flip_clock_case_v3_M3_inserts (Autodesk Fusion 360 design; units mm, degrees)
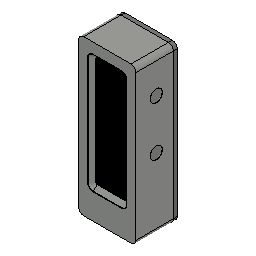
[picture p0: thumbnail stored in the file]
part number: ESP32-C3 supermini
sketch "TFT_PCB_proxy_thickness_1p6_sketch" plane through (0, 0, 0) normal (0, 0, 1) x axis (1, 0, 0)
  line L1 (21.08, 0) -> (0, 0)
  line L2 (21.08, 73.15) -> (21.08, 0)
  line L3 (0, 73.15) -> (21.08, 73.15)
  line L4 (0, 0) -> (0, 73.15)
extrude "Extrude1" new body sketch "TFT_PCB_proxy_thickness_1p6_sketch" along normal blind 1.6 bodies "TFT_PCB_proxy_thickness_1p6"
sketch "M2_hole_locations" plane through (0, 0, 0) normal (0, 0, 1) x axis (1, 0, 0)
  circle C1 centre (2.41, 2.41) radius 1.25
  circle C2 centre (18.67, 2.41) radius 1.25
extrude "Extrude2" cut sketch "M2_hole_locations" blind 5 from offset -1
sketch "LCD_proxy_sketch" plane through (0, 0, 0) normal (0, 0, 1) x axis (1, 0, 0)
  line L1 (18.98, 8.4) -> (1.98, 8.4)
  line L2 (18.98, 68.95) -> (18.98, 8.4)
  line L3 (1.98, 68.95) -> (18.98, 68.95)
  line L4 (1.98, 8.4) -> (1.98, 68.95)
extrude "Extrude3" new body sketch "LCD_proxy_sketch" blind 1.5 from offset 1.6 bodies "LCD_proxy"
sketch "frame_part_1_sketch" plane through (0, 0, 0) normal (0, 0, 1) x axis (1, 0, 0)
  line L1 (1.3, 0) -> (-1.35, 0)
  line L2 (1.3, 69.2) -> (1.3, 0)
  line L3 (-1.35, 69.2) -> (1.3, 69.2)
  line L4 (-1.35, 0) -> (-1.35, 69.2)
extrude "Extrude1" new body sketch "frame_part_1_sketch" blind 3 from offset -4 bodies "01_KHUNG_HA_ESP"
sketch "frame_part_2_sketch" plane through (0, 0, 0) normal (0, 0, 1) x axis (1, 0, 0)
  line L1 (22.43, 0) -> (19.78, 0)
  line L2 (22.43, 69.2) -> (22.43, 0)
  line L3 (19.78, 69.2) -> (22.43, 69.2)
  line L4 (19.78, 0) -> (19.78, 69.2)
extrude "Extrude2" new body sketch "frame_part_2_sketch" blind 3 from offset -4 bodies "frame_part_2"
sketch "frame_part_3_sketch" plane through (0, 0, 0) normal (0, 0, 1) x axis (1, 0, 0)
  line L1 (1.3, 0) -> (0, 0)
  line L2 (1.3, 69.2) -> (1.3, 0)
  line L3 (0, 69.2) -> (1.3, 69.2)
  line L4 (0, 0) -> (0, 69.2)
extrude "Extrude3" new body sketch "frame_part_3_sketch" blind 1 from offset -1 bodies "frame_part_3"
sketch "frame_part_4_sketch" plane through (0, 0, 0) normal (0, 0, 1) x axis (1, 0, 0)
  line L1 (21.08, 0) -> (19.78, 0)
  line L2 (21.08, 69.2) -> (21.08, 0)
  line L3 (19.78, 69.2) -> (21.08, 69.2)
  line L4 (19.78, 0) -> (19.78, 69.2)
extrude "Extrude4" new body sketch "frame_part_4_sketch" blind 1 from offset -1 bodies "frame_part_4"
sketch "frame_part_5_sketch" plane through (0, 0, 0) normal (0, 0, 1) x axis (1, 0, 0)
  line L1 (22.43, 0) -> (-1.35, 0)
  line L2 (22.43, 5.2) -> (22.43, 0)
  line L3 (-1.35, 5.2) -> (22.43, 5.2)
  line L4 (-1.35, 0) -> (-1.35, 5.2)
extrude "Extrude5" new body sketch "frame_part_5_sketch" blind 4 from offset -4 bodies "frame_part_5"
sketch "frame_part_6_sketch" plane through (0, 0, 0) normal (0, 0, 1) x axis (1, 0, 0)
  line L1 (22.43, 66) -> (-1.35, 66)
  line L2 (22.43, 69.2) -> (22.43, 66)
  line L3 (-1.35, 69.2) -> (22.43, 69.2)
  line L4 (-1.35, 66) -> (-1.35, 69.2)
extrude "Extrude6" new body sketch "frame_part_6_sketch" blind 4 from offset -4 bodies "frame_part_6"
sketch "frame_part_7_sketch" plane through (0, 0, 0) normal (0, 0, 1) x axis (1, 0, 0)
  line L1 (22.43, 20.8) -> (-1.35, 20.8)
  line L2 (22.43, 24.8) -> (22.43, 20.8)
  line L3 (-1.35, 24.8) -> (22.43, 24.8)
  line L4 (-1.35, 20.8) -> (-1.35, 24.8)
extrude "Extrude7" new body sketch "frame_part_7_sketch" blind 3 from offset -4 bodies "frame_part_7"
sketch "frame_part_8_sketch" plane through (0, 0, 0) normal (0, 0, 1) x axis (1, 0, 0)
  line L1 (15.88, -1.15) -> (5.2, -1.15)
  line L2 (15.88, 1) -> (15.88, -1.15)
  line L3 (5.2, 1) -> (15.88, 1)
  line L4 (5.2, -1.15) -> (5.2, 1)
extrude "Extrude8" new body sketch "frame_part_8_sketch" blind 2 from offset -4 bodies "frame_part_8"
sketch "frame_part_9_sketch" plane through (0, 0, 0) normal (0, 0, 1) x axis (1, 0, 0)
  line L1 (19.44, -1.15) -> (1.64, -1.15)
  line L2 (19.44, -0.7) -> (19.44, -1.15)
  line L3 (1.64, -0.7) -> (19.44, -0.7)
  line L4 (1.64, -1.15) -> (1.64, -0.7)
extrude "Extrude9" new body sketch "frame_part_9_sketch" blind 4.6 from offset -7.8 bodies "frame_part_9"
sketch "frame_part_10_sketch" plane through (0, 0, 0) normal (0, 0, 1) x axis (1, 0, 0)
  line L1 (4.2, -1.15) -> (1.64, -1.15)
  line L2 (4.2, -0.7) -> (4.2, -1.15)
  line L3 (1.64, -0.7) -> (4.2, -0.7)
  line L4 (1.64, -1.15) -> (1.64, -0.7)
extrude "Extrude10" new body sketch "frame_part_10_sketch" blind 0.4 from offset -8.2 bodies "frame_part_10"
sketch "frame_part_11_sketch" plane through (0, 0, 0) normal (0, 0, 1) x axis (1, 0, 0)
  line L1 (4.2, 21.1) -> (1.64, 21.1)
  line L2 (4.2, 21.55) -> (4.2, 21.1)
  line L3 (1.64, 21.55) -> (4.2, 21.55)
  line L4 (1.64, 21.1) -> (1.64, 21.55)
extrude "Extrude11" new body sketch "frame_part_11_sketch" blind 4.2 from offset -8.2 bodies "frame_part_11"
sketch "frame_part_12_sketch" plane through (0, 0, 0) normal (0, 0, 1) x axis (1, 0, 0)
  line L1 (19.44, -1.15) -> (16.88, -1.15)
  line L2 (19.44, -0.7) -> (19.44, -1.15)
  line L3 (16.88, -0.7) -> (19.44, -0.7)
  line L4 (16.88, -1.15) -> (16.88, -0.7)
extrude "Extrude12" new body sketch "frame_part_12_sketch" blind 0.4 from offset -8.2 bodies "frame_part_12"
sketch "frame_part_13_sketch" plane through (0, 0, 0) normal (0, 0, 1) x axis (1, 0, 0)
  line L1 (19.44, 21.1) -> (16.88, 21.1)
  line L2 (19.44, 21.55) -> (19.44, 21.1)
  line L3 (16.88, 21.55) -> (19.44, 21.55)
  line L4 (16.88, 21.1) -> (16.88, 21.55)
extrude "Extrude13" new body sketch "frame_part_13_sketch" blind 4.2 from offset -8.2 bodies "frame_part_13"
sketch "frame_part_14_sketch" plane through (0, 0, 0) normal (1, 0, 0) x axis (0, 0, -1)
  circle C1 centre (4.1, 9.3) radius 3.9
extrude "Extrude14" new body sketch "frame_part_14_sketch" blind 6 from offset 1.6 bodies "frame_part_14"
sketch "frame_part_15_sketch" plane through (0, 0, 0) normal (1, 0, 0) x axis (0, 0, -1)
  circle C1 centre (4.1, 9.3) radius 3.9
extrude "Extrude15" new body sketch "frame_part_15_sketch" blind 6 from offset 13.48 bodies "frame_part_15"
sketch "frame_part_16_sketch" plane through (0, 0, 0) normal (0, 0, 1) x axis (1, 0, 0)
  line L1 (3, 5.4) -> (0.7, 5.4)
  line L2 (3, 13.2) -> (3, 5.4)
  line L3 (0.7, 13.2) -> (3, 13.2)
  line L4 (0.7, 5.4) -> (0.7, 13.2)
extrude "Extrude16" new body sketch "frame_part_16_sketch" blind 0.6 from offset -0.8 bodies "frame_part_16"
sketch "frame_part_17_sketch" plane through (0, 0, 0) normal (0, 0, 1) x axis (1, 0, 0)
  line L1 (20.38, 5.4) -> (18.08, 5.4)
  line L2 (20.38, 13.2) -> (20.38, 5.4)
  line L3 (18.08, 13.2) -> (20.38, 13.2)
  line L4 (18.08, 5.4) -> (18.08, 13.2)
extrude "Extrude17" new body sketch "frame_part_17_sketch" blind 0.6 from offset -0.8 bodies "frame_part_17"
sketch "frame_part_18_sketch" plane through (0, 0, 0) normal (1, 0, 0) x axis (0, 0, -1)
  circle C1 centre (4.1, 20) radius 3.9
extrude "Extrude18" new body sketch "frame_part_18_sketch" blind 6 from offset 1.6 bodies "frame_part_18"
sketch "frame_part_19_sketch" plane through (0, 0, 0) normal (1, 0, 0) x axis (0, 0, -1)
  circle C1 centre (4.1, 20) radius 3.9
extrude "Extrude19" new body sketch "frame_part_19_sketch" blind 6 from offset 13.48 bodies "frame_part_19"
sketch "frame_part_20_sketch" plane through (0, 0, 0) normal (0, 0, 1) x axis (1, 0, 0)
  line L1 (3, 16.1) -> (0.7, 16.1)
  line L2 (3, 23.9) -> (3, 16.1)
  line L3 (0.7, 23.9) -> (3, 23.9)
  line L4 (0.7, 16.1) -> (0.7, 23.9)
extrude "Extrude20" new body sketch "frame_part_20_sketch" blind 0.6 from offset -0.8 bodies "frame_part_20"
sketch "frame_part_21_sketch" plane through (0, 0, 0) normal (0, 0, 1) x axis (1, 0, 0)
  line L1 (20.38, 16.1) -> (18.08, 16.1)
  line L2 (20.38, 23.9) -> (20.38, 16.1)
  line L3 (18.08, 23.9) -> (20.38, 23.9)
  line L4 (18.08, 16.1) -> (18.08, 23.9)
extrude "Extrude21" new body sketch "frame_part_21_sketch" blind 0.6 from offset -0.8 bodies "frame_part_21"
sketch "frame_part_22_sketch" plane through (0, 0, 0) normal (1, 0, 0) x axis (0, 0, -1)
  circle C1 centre (5, 33) radius 3.9
extrude "Extrude22" new body sketch "frame_part_22_sketch" blind 6.5 from offset -1.35 bodies "frame_part_22"
sketch "frame_part_23_sketch" plane through (0, 0, 0) normal (1, 0, 0) x axis (0, 0, -1)
  circle C1 centre (5, 33) radius 3.9
extrude "Extrude23" new body sketch "frame_part_23_sketch" blind 6.5 from offset 15.93 bodies "frame_part_23"
sketch "frame_part_24_sketch" plane through (0, 0, 0) normal (1, 0, 0) x axis (0, 0, -1)
  circle C1 centre (5, 58) radius 3.9
extrude "Extrude24" new body sketch "frame_part_24_sketch" blind 6.5 from offset -1.35 bodies "frame_part_24"
sketch "frame_part_25_sketch" plane through (0, 0, 0) normal (1, 0, 0) x axis (0, 0, -1)
  circle C1 centre (5, 58) radius 3.9
extrude "Extrude25" new body sketch "frame_part_25_sketch" blind 6.5 from offset 15.93 bodies "frame_part_25"
sketch "frame_part_26_sketch" plane through (0, 0, 0) normal (0, 0, 1) x axis (1, 0, 0)
  circle C1 centre (3, 42) radius 3.9
extrude "Extrude26" new body sketch "frame_part_26_sketch" blind 8.5 from offset -12.4 bodies "frame_part_26"
sketch "frame_part_27_sketch" plane through (0, 0, 0) normal (0, 0, 1) x axis (1, 0, 0)
  circle C1 centre (18.08, 42) radius 3.9
extrude "Extrude27" new body sketch "frame_part_27_sketch" blind 8.5 from offset -12.4 bodies "frame_part_27"
sketch "frame_part_28_sketch" plane through (0, 0, 0) normal (0, 0, 1) x axis (1, 0, 0)
  circle C1 centre (3, 66) radius 3.9
extrude "Extrude28" new body sketch "frame_part_28_sketch" blind 8.5 from offset -12.4 bodies "frame_part_28"
sketch "frame_part_29_sketch" plane through (0, 0, 0) normal (0, 0, 1) x axis (1, 0, 0)
  circle C1 centre (18.08, 66) radius 3.9
extrude "Extrude29" new body sketch "frame_part_29_sketch" blind 8.5 from offset -12.4 bodies "frame_part_29"
combine "Combine1" bodies "frame_part_2", "frame_part_3", "frame_part_4", "frame_part_5", "frame_part_6", "frame_part_7", "frame_part_8", "frame_part_9"
sketch "frame_cut_1_sketch" plane through (0, 0, 0) normal (0, 0, 1) x axis (1, 0, 0)
  circle C1 centre (2.41, 2.41) radius 1.1
extrude "Extrude30" cut sketch "frame_cut_1_sketch" blind 12 from offset -10
sketch "frame_cut_2_sketch" plane through (0, 0, 0) normal (0, 0, 1) x axis (1, 0, 0)
  circle C1 centre (18.67, 2.41) radius 1.1
extrude "Extrude31" cut sketch "frame_cut_2_sketch" blind 12 from offset -10
sketch "TFT_M2_nut_pocket_1_sketch" plane through (0, 0, 0) normal (0, 0, 1) x axis (1, 0, 0)
  line L1 (3.6224, 4.51) -> (4.8349, 2.41)
  line L2 (1.1976, 4.51) -> (3.6224, 4.51)
  line L3 (-0.0149, 2.41) -> (1.1976, 4.51)
  line L4 (1.1976, 0.31) -> (-0.0149, 2.41)
  line L5 (3.6224, 0.31) -> (1.1976, 0.31)
  line L6 (4.8349, 2.41) -> (3.6224, 0.31)
extrude "Extrude32" cut sketch "TFT_M2_nut_pocket_1_sketch" blind 1.75 from offset -4
sketch "TFT_M2_nut_pocket_2_sketch" plane through (0, 0, 0) normal (0, 0, 1) x axis (1, 0, 0)
  line L1 (19.8824, 4.51) -> (21.0949, 2.41)
  line L2 (17.4576, 4.51) -> (19.8824, 4.51)
  line L3 (16.2451, 2.41) -> (17.4576, 4.51)
  line L4 (17.4576, 0.31) -> (16.2451, 2.41)
  line L5 (19.8824, 0.31) -> (17.4576, 0.31)
  line L6 (21.0949, 2.41) -> (19.8824, 0.31)
extrude "Extrude33" cut sketch "TFT_M2_nut_pocket_2_sketch" blind 1.75 from offset -4
sketch "frame_cut_5_sketch" plane through (0, 0, 0) normal (0, 0, 1) x axis (1, 0, 0)
  line L1 (1.6, 6) -> (-2, 6)
  line L2 (1.6, 12.6) -> (1.6, 6)
  line L3 (-2, 12.6) -> (1.6, 12.6)
  line L4 (-2, 6) -> (-2, 12.6)
extrude "Extrude34" cut sketch "frame_cut_5_sketch" blind 7.2 from offset -8
sketch "frame_cut_6_sketch" plane through (0, 0, 0) normal (0, 0, 1) x axis (1, 0, 0)
  line L1 (23.1, 6) -> (19.48, 6)
  line L2 (23.1, 12.6) -> (23.1, 6)
  line L3 (19.48, 12.6) -> (23.1, 12.6)
  line L4 (19.48, 6) -> (19.48, 12.6)
extrude "Extrude35" cut sketch "frame_cut_6_sketch" blind 7.2 from offset -8
sketch "frame_cut_7_sketch" plane through (0, 0, 0) normal (1, 0, 0) x axis (0, 0, -1)
  circle C1 centre (4.1, 9.3) radius 2
extrude "Extrude36" cut sketch "frame_cut_7_sketch" blind 5 from offset 1.6
sketch "frame_cut_8_sketch" plane through (0, 0, 0) normal (1, 0, 0) x axis (0, 0, -1)
  circle C1 centre (4.1, 9.3) radius 2
extrude "Extrude37" cut sketch "frame_cut_8_sketch" blind 5 from offset 14.48
sketch "frame_cut_9_sketch" plane through (0, 0, 0) normal (1, 0, 0) x axis (0, 0, -1)
  circle C1 centre (4.1, 9.3) radius 1.7
extrude "Extrude38" cut sketch "frame_cut_9_sketch" blind 5.3 from offset 1.6
sketch "frame_cut_10_sketch" plane through (0, 0, 0) normal (1, 0, 0) x axis (0, 0, -1)
  circle C1 centre (4.1, 9.3) radius 1.7
extrude "Extrude39" cut sketch "frame_cut_10_sketch" blind 5.3 from offset 14.18
sketch "frame_cut_11_sketch" plane through (0, 0, 0) normal (0, 0, 1) x axis (1, 0, 0)
  line L1 (1.6, 16.7) -> (-2, 16.7)
  line L2 (1.6, 23.3) -> (1.6, 16.7)
  line L3 (-2, 23.3) -> (1.6, 23.3)
  line L4 (-2, 16.7) -> (-2, 23.3)
extrude "Extrude40" cut sketch "frame_cut_11_sketch" blind 7.2 from offset -8
sketch "frame_cut_12_sketch" plane through (0, 0, 0) normal (0, 0, 1) x axis (1, 0, 0)
  line L1 (23.1, 16.7) -> (19.48, 16.7)
  line L2 (23.1, 23.3) -> (23.1, 16.7)
  line L3 (19.48, 23.3) -> (23.1, 23.3)
  line L4 (19.48, 16.7) -> (19.48, 23.3)
extrude "Extrude41" cut sketch "frame_cut_12_sketch" blind 7.2 from offset -8
sketch "frame_cut_13_sketch" plane through (0, 0, 0) normal (1, 0, 0) x axis (0, 0, -1)
  circle C1 centre (4.1, 20) radius 2
extrude "Extrude42" cut sketch "frame_cut_13_sketch" blind 5 from offset 1.6
sketch "frame_cut_14_sketch" plane through (0, 0, 0) normal (1, 0, 0) x axis (0, 0, -1)
  circle C1 centre (4.1, 20) radius 2
extrude "Extrude43" cut sketch "frame_cut_14_sketch" blind 5 from offset 14.48
sketch "frame_cut_15_sketch" plane through (0, 0, 0) normal (1, 0, 0) x axis (0, 0, -1)
  circle C1 centre (4.1, 20) radius 1.7
extrude "Extrude44" cut sketch "frame_cut_15_sketch" blind 5.3 from offset 1.6
sketch "frame_cut_16_sketch" plane through (0, 0, 0) normal (1, 0, 0) x axis (0, 0, -1)
  circle C1 centre (4.1, 20) radius 1.7
extrude "Extrude45" cut sketch "frame_cut_16_sketch" blind 5.3 from offset 14.18
sketch "frame_cut_17_sketch" plane through (0, 0, 0) normal (1, 0, 0) x axis (0, 0, -1)
  circle C1 centre (5, 33) radius 2
extrude "Extrude46" cut sketch "frame_cut_17_sketch" blind 5 from offset -1.35
sketch "frame_cut_18_sketch" plane through (0, 0, 0) normal (1, 0, 0) x axis (0, 0, -1)
  circle C1 centre (5, 33) radius 2
extrude "Extrude47" cut sketch "frame_cut_18_sketch" blind 5 from offset 17.43
sketch "frame_cut_19_sketch" plane through (0, 0, 0) normal (1, 0, 0) x axis (0, 0, -1)
  circle C1 centre (5, 33) radius 1.7
extrude "Extrude48" cut sketch "frame_cut_19_sketch" blind 6 from offset -1.35
sketch "frame_cut_20_sketch" plane through (0, 0, 0) normal (1, 0, 0) x axis (0, 0, -1)
  circle C1 centre (5, 33) radius 1.7
extrude "Extrude49" cut sketch "frame_cut_20_sketch" blind 6 from offset 16.43
sketch "frame_cut_21_sketch" plane through (0, 0, 0) normal (1, 0, 0) x axis (0, 0, -1)
  circle C1 centre (5, 58) radius 2
extrude "Extrude50" cut sketch "frame_cut_21_sketch" blind 5 from offset -1.35
sketch "frame_cut_22_sketch" plane through (0, 0, 0) normal (1, 0, 0) x axis (0, 0, -1)
  circle C1 centre (5, 58) radius 2
extrude "Extrude51" cut sketch "frame_cut_22_sketch" blind 5 from offset 17.43
sketch "frame_cut_23_sketch" plane through (0, 0, 0) normal (1, 0, 0) x axis (0, 0, -1)
  circle C1 centre (5, 58) radius 1.7
extrude "Extrude52" cut sketch "frame_cut_23_sketch" blind 6 from offset -1.35
sketch "frame_cut_24_sketch" plane through (0, 0, 0) normal (1, 0, 0) x axis (0, 0, -1)
  circle C1 centre (5, 58) radius 1.7
extrude "Extrude53" cut sketch "frame_cut_24_sketch" blind 6 from offset 16.43
sketch "frame_cut_25_sketch" plane through (0, 0, 0) normal (0, 0, 1) x axis (1, 0, 0)
  circle C1 centre (3, 42) radius 2
extrude "Extrude54" cut sketch "frame_cut_25_sketch" blind 5 from offset -12.4
sketch "frame_cut_26_sketch" plane through (0, 0, 0) normal (0, 0, 1) x axis (1, 0, 0)
  circle C1 centre (18.08, 42) radius 2
extrude "Extrude55" cut sketch "frame_cut_26_sketch" blind 5 from offset -12.4
sketch "frame_cut_27_sketch" plane through (0, 0, 0) normal (0, 0, 1) x axis (1, 0, 0)
  circle C1 centre (3, 66) radius 2
extrude "Extrude56" cut sketch "frame_cut_27_sketch" blind 5 from offset -12.4
sketch "frame_cut_28_sketch" plane through (0, 0, 0) normal (0, 0, 1) x axis (1, 0, 0)
  circle C1 centre (18.08, 66) radius 2
extrude "Extrude57" cut sketch "frame_cut_28_sketch" blind 5 from offset -12.4
sketch "frame_cut_29_sketch" plane through (0, 0, 0) normal (0, 0, 1) x axis (1, 0, 0)
  circle C1 centre (3, 42) radius 1.7
extrude "Extrude58" cut sketch "frame_cut_29_sketch" blind 5.5 from offset -12.4
sketch "frame_cut_30_sketch" plane through (0, 0, 0) normal (0, 0, 1) x axis (1, 0, 0)
  circle C1 centre (18.08, 42) radius 1.7
extrude "Extrude59" cut sketch "frame_cut_30_sketch" blind 5.5 from offset -12.4
sketch "frame_cut_31_sketch" plane through (0, 0, 0) normal (0, 0, 1) x axis (1, 0, 0)
  circle C1 centre (3, 66) radius 1.7
extrude "Extrude60" cut sketch "frame_cut_31_sketch" blind 5.5 from offset -12.4
sketch "frame_cut_32_sketch" plane through (0, 0, 0) normal (0, 0, 1) x axis (1, 0, 0)
  circle C1 centre (18.08, 66) radius 1.7
extrude "Extrude61" cut sketch "frame_cut_32_sketch" blind 5.5 from offset -12.4
sketch "keeper_part_1_sketch" plane through (0, 0, 0) normal (0, 0, 1) x axis (1, 0, 0)
  line L1 (1.55, 0.2) -> (-1.25, 0.2)
  line L2 (1.55, 24.7) -> (1.55, 0.2)
  line L3 (-1.25, 24.7) -> (1.55, 24.7)
  line L4 (-1.25, 0.2) -> (-1.25, 24.7)
extrude "Extrude1" new body sketch "keeper_part_1_sketch" blind 2 from offset -11.6 bodies "02_NEP_ESP"
sketch "keeper_part_2_sketch" plane through (0, 0, 0) normal (0, 0, 1) x axis (1, 0, 0)
  line L1 (22.33, 0.2) -> (19.53, 0.2)
  line L2 (22.33, 24.7) -> (22.33, 0.2)
  line L3 (19.53, 24.7) -> (22.33, 24.7)
  line L4 (19.53, 0.2) -> (19.53, 24.7)
extrude "Extrude2" new body sketch "keeper_part_2_sketch" blind 2 from offset -11.6 bodies "keeper_part_2"
sketch "keeper_part_3_sketch" plane through (0, 0, 0) normal (0, 0, 1) x axis (1, 0, 0)
  line L1 (22.33, 23) -> (-1.25, 23)
  line L2 (22.33, 24.7) -> (22.33, 23)
  line L3 (-1.25, 24.7) -> (22.33, 24.7)
  line L4 (-1.25, 23) -> (-1.25, 24.7)
extrude "Extrude3" new body sketch "keeper_part_3_sketch" blind 2 from offset -11.6 bodies "keeper_part_3"
sketch "keeper_part_4_sketch" plane through (0, 0, 0) normal (0, 0, 1) x axis (1, 0, 0)
  line L1 (4.2, 0.2) -> (-1.25, 0.2)
  line L2 (4.2, 3.5) -> (4.2, 0.2)
  line L3 (-1.25, 3.5) -> (4.2, 3.5)
  line L4 (-1.25, 0.2) -> (-1.25, 3.5)
extrude "Extrude4" new body sketch "keeper_part_4_sketch" blind 2 from offset -11.6 bodies "keeper_part_4"
sketch "keeper_part_5_sketch" plane through (0, 0, 0) normal (0, 0, 1) x axis (1, 0, 0)
  line L1 (22.33, 0.2) -> (16.88, 0.2)
  line L2 (22.33, 3.5) -> (22.33, 0.2)
  line L3 (16.88, 3.5) -> (22.33, 3.5)
  line L4 (16.88, 0.2) -> (16.88, 3.5)
extrude "Extrude5" new body sketch "keeper_part_5_sketch" blind 2 from offset -11.6 bodies "keeper_part_5"
sketch "keeper_part_6_sketch" plane through (0, 0, 0) normal (0, 0, 1) x axis (1, 0, 0)
  line L1 (4.2, -1.15) -> (0.69, -1.15)
  line L2 (4.2, 0.2) -> (4.2, -1.15)
  line L3 (0.69, 0.2) -> (4.2, 0.2)
  line L4 (0.69, -1.15) -> (0.69, 0.2)
extrude "Extrude6" new body sketch "keeper_part_6_sketch" blind 2 from offset -11.6 bodies "keeper_part_6"
sketch "keeper_part_7_sketch" plane through (0, 0, 0) normal (0, 0, 1) x axis (1, 0, 0)
  line L1 (20.39, -1.15) -> (16.88, -1.15)
  line L2 (20.39, 0.2) -> (20.39, -1.15)
  line L3 (16.88, 0.2) -> (20.39, 0.2)
  line L4 (16.88, -1.15) -> (16.88, 0.2)
extrude "Extrude7" new body sketch "keeper_part_7_sketch" blind 2 from offset -11.6 bodies "keeper_part_7"
sketch "keeper_part_8_sketch" plane through (0, 0, 0) normal (0, 0, 1) x axis (1, 0, 0)
  line L1 (4.2, 21.1) -> (-1.25, 21.1)
  line L2 (4.2, 23) -> (4.2, 21.1)
  line L3 (-1.25, 23) -> (4.2, 23)
  line L4 (-1.25, 21.1) -> (-1.25, 23)
extrude "Extrude8" new body sketch "keeper_part_8_sketch" blind 2 from offset -11.6 bodies "keeper_part_8"
sketch "keeper_part_9_sketch" plane through (0, 0, 0) normal (0, 0, 1) x axis (1, 0, 0)
  line L1 (22.33, 21.1) -> (16.88, 21.1)
  line L2 (22.33, 23) -> (22.33, 21.1)
  line L3 (16.88, 23) -> (22.33, 23)
  line L4 (16.88, 21.1) -> (16.88, 23)
extrude "Extrude9" new body sketch "keeper_part_9_sketch" blind 2 from offset -11.6 bodies "keeper_part_9"
sketch "keeper_part_10_sketch" plane through (0, 0, 0) normal (0, 0, 1) x axis (1, 0, 0)
  line L1 (4.2, -1.15) -> (1.64, -1.15)
  line L2 (4.2, -0.7) -> (4.2, -1.15)
  line L3 (1.64, -0.7) -> (4.2, -0.7)
  line L4 (1.64, -1.15) -> (1.64, -0.7)
extrude "Extrude10" new body sketch "keeper_part_10_sketch" blind 0.5 from offset -9.6 bodies "keeper_part_10"
sketch "keeper_part_11_sketch" plane through (0, 0, 0) normal (0, 0, 1) x axis (1, 0, 0)
  line L1 (4.2, 21.1) -> (1.64, 21.1)
  line L2 (4.2, 21.55) -> (4.2, 21.1)
  line L3 (1.64, 21.55) -> (4.2, 21.55)
  line L4 (1.64, 21.1) -> (1.64, 21.55)
extrude "Extrude11" new body sketch "keeper_part_11_sketch" blind 0.5 from offset -9.6 bodies "keeper_part_11"
sketch "keeper_part_12_sketch" plane through (0, 0, 0) normal (0, 0, 1) x axis (1, 0, 0)
  line L1 (4.2, -1.6) -> (1.64, -1.6)
  line L2 (4.2, -1.15) -> (4.2, -1.6)
  line L3 (1.64, -1.15) -> (4.2, -1.15)
  line L4 (1.64, -1.6) -> (1.64, -1.15)
extrude "Extrude12" new body sketch "keeper_part_12_sketch" blind 1.5 from offset -9.6 bodies "keeper_part_12"
sketch "keeper_part_13_sketch" plane through (0, 0, 0) normal (0, 0, 1) x axis (1, 0, 0)
  line L1 (4.2, 21.55) -> (1.64, 21.55)
  line L2 (4.2, 22) -> (4.2, 21.55)
  line L3 (1.64, 22) -> (4.2, 22)
  line L4 (1.64, 21.55) -> (1.64, 22)
extrude "Extrude13" new body sketch "keeper_part_13_sketch" blind 1.5 from offset -9.6 bodies "keeper_part_13"
sketch "keeper_part_14_sketch" plane through (0, 0, 0) normal (0, 0, 1) x axis (1, 0, 0)
  line L1 (19.44, -1.15) -> (16.88, -1.15)
  line L2 (19.44, -0.7) -> (19.44, -1.15)
  line L3 (16.88, -0.7) -> (19.44, -0.7)
  line L4 (16.88, -1.15) -> (16.88, -0.7)
extrude "Extrude14" new body sketch "keeper_part_14_sketch" blind 0.5 from offset -9.6 bodies "keeper_part_14"
sketch "keeper_part_15_sketch" plane through (0, 0, 0) normal (0, 0, 1) x axis (1, 0, 0)
  line L1 (19.44, 21.1) -> (16.88, 21.1)
  line L2 (19.44, 21.55) -> (19.44, 21.1)
  line L3 (16.88, 21.55) -> (19.44, 21.55)
  line L4 (16.88, 21.1) -> (16.88, 21.55)
extrude "Extrude15" new body sketch "keeper_part_15_sketch" blind 0.5 from offset -9.6 bodies "keeper_part_15"
sketch "keeper_part_16_sketch" plane through (0, 0, 0) normal (0, 0, 1) x axis (1, 0, 0)
  line L1 (19.44, -1.6) -> (16.88, -1.6)
  line L2 (19.44, -1.15) -> (19.44, -1.6)
  line L3 (16.88, -1.15) -> (19.44, -1.15)
  line L4 (16.88, -1.6) -> (16.88, -1.15)
extrude "Extrude16" new body sketch "keeper_part_16_sketch" blind 1.5 from offset -9.6 bodies "keeper_part_16"
sketch "keeper_part_17_sketch" plane through (0, 0, 0) normal (0, 0, 1) x axis (1, 0, 0)
  line L1 (19.44, 21.55) -> (16.88, 21.55)
  line L2 (19.44, 22) -> (19.44, 21.55)
  line L3 (16.88, 22) -> (19.44, 22)
  line L4 (16.88, 21.55) -> (16.88, 22)
extrude "Extrude17" new body sketch "keeper_part_17_sketch" blind 1.5 from offset -9.6 bodies "keeper_part_17"
sketch "keeper_part_18_sketch" plane through (0, 0, 0) normal (0, 0, 1) x axis (1, 0, 0)
  line L1 (1.49, -1.15) -> (0.69, -1.15)
  line L2 (1.49, -0.7) -> (1.49, -1.15)
  line L3 (0.69, -0.7) -> (1.49, -0.7)
  line L4 (0.69, -1.15) -> (0.69, -0.7)
extrude "Extrude18" new body sketch "keeper_part_18_sketch" blind 1.5 from offset -9.6 bodies "keeper_part_18"
sketch "keeper_part_19_sketch" plane through (0, 0, 0) normal (0, 0, 1) x axis (1, 0, 0)
  line L1 (1.49, 21.1) -> (0.69, 21.1)
  line L2 (1.49, 21.55) -> (1.49, 21.1)
  line L3 (0.69, 21.55) -> (1.49, 21.55)
  line L4 (0.69, 21.1) -> (0.69, 21.55)
extrude "Extrude19" new body sketch "keeper_part_19_sketch" blind 1.5 from offset -9.6 bodies "keeper_part_19"
sketch "keeper_part_20_sketch" plane through (0, 0, 0) normal (0, 0, 1) x axis (1, 0, 0)
  line L1 (20.39, -1.15) -> (19.59, -1.15)
  line L2 (20.39, -0.7) -> (20.39, -1.15)
  line L3 (19.59, -0.7) -> (20.39, -0.7)
  line L4 (19.59, -1.15) -> (19.59, -0.7)
extrude "Extrude20" new body sketch "keeper_part_20_sketch" blind 1.5 from offset -9.6 bodies "keeper_part_20"
sketch "keeper_part_21_sketch" plane through (0, 0, 0) normal (0, 0, 1) x axis (1, 0, 0)
  line L1 (20.39, 21.1) -> (19.59, 21.1)
  line L2 (20.39, 21.55) -> (20.39, 21.1)
  line L3 (19.59, 21.55) -> (20.39, 21.55)
  line L4 (19.59, 21.1) -> (19.59, 21.55)
extrude "Extrude21" new body sketch "keeper_part_21_sketch" blind 1.5 from offset -9.6 bodies "keeper_part_21"
sketch "keeper_part_22_sketch" plane through (0, 0, 0) normal (0, 0, 1) x axis (1, 0, 0)
  line L1 (1.6, 6.2) -> (0, 6.2)
  line L2 (1.6, 12.4) -> (1.6, 6.2)
  line L3 (0, 12.4) -> (1.6, 12.4)
  line L4 (0, 6.2) -> (0, 12.4)
extrude "Extrude22" new body sketch "keeper_part_22_sketch" blind 6.8 from offset -7.8 bodies "keeper_part_22"
sketch "keeper_part_23_sketch" plane through (0, 0, 0) normal (0, 0, 1) x axis (1, 0, 0)
  line L1 (21.08, 6.2) -> (19.48, 6.2)
  line L2 (21.08, 12.4) -> (21.08, 6.2)
  line L3 (19.48, 12.4) -> (21.08, 12.4)
  line L4 (19.48, 6.2) -> (19.48, 12.4)
extrude "Extrude23" new body sketch "keeper_part_23_sketch" blind 6.8 from offset -7.8 bodies "keeper_part_23"
sketch "keeper_part_24_sketch" plane through (0, 0, 0) normal (0, 0, 1) x axis (1, 0, 0)
  line L1 (1.25, 6.2) -> (0, 6.2)
  line L2 (1.25, 12.4) -> (1.25, 6.2)
  line L3 (0, 12.4) -> (1.25, 12.4)
  line L4 (0, 6.2) -> (0, 12.4)
extrude "Extrude24" new body sketch "keeper_part_24_sketch" blind 3.8 from offset -11.6 bodies "keeper_part_24"
sketch "keeper_part_25_sketch" plane through (0, 0, 0) normal (0, 0, 1) x axis (1, 0, 0)
  line L1 (21.08, 6.2) -> (19.83, 6.2)
  line L2 (21.08, 12.4) -> (21.08, 6.2)
  line L3 (19.83, 12.4) -> (21.08, 12.4)
  line L4 (19.83, 6.2) -> (19.83, 12.4)
extrude "Extrude25" new body sketch "keeper_part_25_sketch" blind 3.8 from offset -11.6 bodies "keeper_part_25"
sketch "keeper_part_26_sketch" plane through (0, 0, 0) normal (0, 0, 1) x axis (1, 0, 0)
  line L1 (1.6, 16.9) -> (0, 16.9)
  line L2 (1.6, 23.1) -> (1.6, 16.9)
  line L3 (0, 23.1) -> (1.6, 23.1)
  line L4 (0, 16.9) -> (0, 23.1)
extrude "Extrude26" new body sketch "keeper_part_26_sketch" blind 6.8 from offset -7.8 bodies "keeper_part_26"
sketch "keeper_part_27_sketch" plane through (0, 0, 0) normal (0, 0, 1) x axis (1, 0, 0)
  line L1 (21.08, 16.9) -> (19.48, 16.9)
  line L2 (21.08, 23.1) -> (21.08, 16.9)
  line L3 (19.48, 23.1) -> (21.08, 23.1)
  line L4 (19.48, 16.9) -> (19.48, 23.1)
extrude "Extrude27" new body sketch "keeper_part_27_sketch" blind 6.8 from offset -7.8 bodies "keeper_part_27"
sketch "keeper_part_28_sketch" plane through (0, 0, 0) normal (0, 0, 1) x axis (1, 0, 0)
  line L1 (1.25, 16.9) -> (0, 16.9)
  line L2 (1.25, 23.1) -> (1.25, 16.9)
  line L3 (0, 23.1) -> (1.25, 23.1)
  line L4 (0, 16.9) -> (0, 23.1)
extrude "Extrude28" new body sketch "keeper_part_28_sketch" blind 3.8 from offset -11.6 bodies "keeper_part_28"
sketch "keeper_part_29_sketch" plane through (0, 0, 0) normal (0, 0, 1) x axis (1, 0, 0)
  line L1 (21.08, 16.9) -> (19.83, 16.9)
  line L2 (21.08, 23.1) -> (21.08, 16.9)
  line L3 (19.83, 23.1) -> (21.08, 23.1)
  line L4 (19.83, 16.9) -> (19.83, 23.1)
extrude "Extrude29" new body sketch "keeper_part_29_sketch" blind 3.8 from offset -11.6 bodies "keeper_part_29"
combine "Combine1" bodies "keeper_part_2", "keeper_part_3", "keeper_part_4", "keeper_part_5", "keeper_part_6", "keeper_part_7", "keeper_part_8", "keeper_part_9"
sketch "keeper_cut_1_sketch" plane through (0, 0, 0) normal (1, 0, 0) x axis (0, 0, -1)
  circle C1 centre (4.1, 9.3) radius 1.7
extrude "Extrude30" cut sketch "keeper_cut_1_sketch" blind 1.8 from offset -0.1
sketch "keeper_cut_2_sketch" plane through (0, 0, 0) normal (1, 0, 0) x axis (0, 0, -1)
  circle C1 centre (4.1, 9.3) radius 1.7
extrude "Extrude31" cut sketch "keeper_cut_2_sketch" blind 1.8 from offset 19.38
sketch "keeper_cut_3_sketch" plane through (0, 0, 0) normal (1, 0, 0) x axis (0, 0, -1)
  circle C1 centre (4.1, 20) radius 1.7
extrude "Extrude32" cut sketch "keeper_cut_3_sketch" blind 1.8 from offset -0.1
sketch "keeper_cut_4_sketch" plane through (0, 0, 0) normal (1, 0, 0) x axis (0, 0, -1)
  circle C1 centre (4.1, 20) radius 1.7
extrude "Extrude33" cut sketch "keeper_cut_4_sketch" blind 1.8 from offset 19.38
sketch "Case_outer_R3_sketch" plane through (0, 0, 0) normal (0, 0, 1) x axis (1, 0, 0)
  line L1 (22.53, -2.7) -> (-1.45, -2.7)
  line L2 (25.03, 73.35) -> (25.03, -0.2)
  line L3 (-1.45, 75.85) -> (22.53, 75.85)
  line L4 (-3.95, -0.2) -> (-3.95, 73.35)
  arc A1 centre (22.53, -0.2) radius 2.5 clockwise from (25.03, -0.2) to (22.53, -2.7)
  arc A2 centre (22.53, 73.35) radius 2.5 clockwise from (22.53, 75.85) to (25.03, 73.35)
  arc A3 centre (-1.45, 73.35) radius 2.5 clockwise from (-3.95, 73.35) to (-1.45, 75.85)
  arc A4 centre (-1.45, -0.2) radius 2.5 clockwise from (-1.45, -2.7) to (-3.95, -0.2)
extrude "Extrude1" new body sketch "Case_outer_R3_sketch" blind 18.9 from offset -13.6 bodies "M3_CONTACT_PADS"
sketch "Case_cavity_wall_2mm_sketch" plane through (0, 0, 0) normal (0, 0, 1) x axis (1, 0, 0)
  line L1 (22.23, -1.2) -> (-1.15, -1.2)
  line L2 (23.03, 73.55) -> (23.03, -0.4)
  line L3 (-1.15, 74.35) -> (22.23, 74.35)
  line L4 (-1.95, -0.4) -> (-1.95, 73.55)
  arc A1 centre (22.23, -0.4) radius 0.8 clockwise from (23.03, -0.4) to (22.23, -1.2)
  arc A2 centre (22.23, 73.55) radius 0.8 clockwise from (22.23, 74.35) to (23.03, 73.55)
  arc A3 centre (-1.15, 73.55) radius 0.8 clockwise from (-1.95, 73.55) to (-1.15, 74.35)
  arc A4 centre (-1.15, -0.4) radius 0.8 clockwise from (-1.15, -1.2) to (-1.95, -0.4)
extrude "Extrude2" cut blind 17 from offset -13.7
sketch "Case_mount_boss_1_sketch" plane through (0, 0, 0) normal (0, 0, 1) x axis (1, 0, 0)
  line L1 (1.3, 5.5) -> (0, 5.5)
  line L2 (1.3, 69.2) -> (1.3, 5.5)
  line L3 (0, 69.2) -> (1.3, 69.2)
  line L4 (0, 5.5) -> (0, 69.2)
extrude "Extrude3" new body sketch "Case_mount_boss_1_sketch" blind 1.8 from offset 1.6 bodies "Case_mount_boss_1"
sketch "Case_mount_boss_2_sketch" plane through (0, 0, 0) normal (0, 0, 1) x axis (1, 0, 0)
  line L1 (21.08, 5.5) -> (19.78, 5.5)
  line L2 (21.08, 69.2) -> (21.08, 5.5)
  line L3 (19.78, 69.2) -> (21.08, 69.2)
  line L4 (19.78, 5.5) -> (19.78, 69.2)
extrude "Extrude4" new body sketch "Case_mount_boss_2_sketch" blind 1.8 from offset 1.6 bodies "Case_mount_boss_2"
combine "Combine1" bodies "Case_mount_boss_1", "Case_mount_boss_2"
sketch "Case_cut_1_sketch" plane through (0, 0, 0) normal (0, 0, 1) x axis (1, 0, 0)
  line L1 (20.68, -1.8) -> (0.4, -1.8)
  line L2 (20.68, -0.6) -> (20.68, -1.8)
  line L3 (0.4, -0.6) -> (20.68, -0.6)
  line L4 (0.4, -1.8) -> (0.4, -0.6)
extrude "Extrude5" cut sketch "Case_cut_1_sketch" blind 12.1 from offset -13.7
sketch "Case_cut_2_sketch" plane through (0, 0, 0) normal (0, 0, 1) x axis (1, 0, 0)
  line L1 (17.577, 12.405) -> (3.38, 12.405)
  line L2 (18.177, 67.7) -> (18.177, 13.005)
  line L3 (3.38, 68.3) -> (17.577, 68.3)
  line L4 (2.78, 13.005) -> (2.78, 67.7)
  arc A1 centre (17.577, 13.005) radius 0.6 clockwise from (18.177, 13.005) to (17.577, 12.405)
  arc A2 centre (17.577, 67.7) radius 0.6 clockwise from (17.577, 68.3) to (18.177, 67.7)
  arc A3 centre (3.38, 67.7) radius 0.6 clockwise from (2.78, 67.7) to (3.38, 68.3)
  arc A4 centre (3.38, 13.005) radius 0.6 clockwise from (3.38, 12.405) to (2.78, 13.005)
extrude "Extrude6" cut sketch "Case_cut_2_sketch" blind 2.3 from offset 3.2
sketch "Case_cut_3_sketch" plane through (0, 0, 0) normal (0, 1, 0) x axis (1, 0, 0)
  line L1 (13.54, 8.8) -> (7.54, 8.8)
  line L2 (15.34, 10.8) -> (15.34, 10.6)
  line L3 (7.54, 12.6) -> (13.54, 12.6)
  line L4 (5.74, 10.6) -> (5.74, 10.8)
  arc A1 centre (13.54, 10.6) radius 1.8 clockwise from (15.34, 10.6) to (13.54, 8.8)
  arc A2 centre (13.54, 10.8) radius 1.8 clockwise from (13.54, 12.6) to (15.34, 10.8)
  arc A3 centre (7.54, 10.8) radius 1.8 clockwise from (5.74, 10.8) to (7.54, 12.6)
  arc A4 centre (7.54, 10.6) radius 1.8 clockwise from (7.54, 8.8) to (5.74, 10.6)
extrude "Extrude7" cut sketch "Case_cut_3_sketch" blind 4.1 from offset -3.1
sketch "Case_cut_4_sketch" plane through (0, 0, 0) normal (0, 0, 1) x axis (1, 0, 0)
  line L1 (15.34, -3.1) -> (5.74, -3.1)
  line L2 (15.34, 1) -> (15.34, -3.1)
  line L3 (5.74, 1) -> (15.34, 1)
  line L4 (5.74, -3.1) -> (5.74, 1)
extrude "Extrude8" cut sketch "Case_cut_4_sketch" blind 3 from offset -13.7
sketch "Case_cut_5_sketch" plane through (0, 0, 0) normal (1, 0, 0) x axis (0, 0, -1)
  circle C1 centre (5, 33) radius 1.7
extrude "Extrude9" cut sketch "Case_cut_5_sketch" blind 29.18 from offset -4.05
work_plane "WorkPlane1" AlongDistance -3.95
sketch "Case_cut_6_profile_0" plane through (-3.95, 0, 0) normal (1, 0, 0) x axis (0, 0, -1)
  circle C1 centre (5, 33) radius 3.1
work_plane "WorkPlane2" AlongDistance -2.55
sketch "Case_cut_6_profile_1" plane through (-2.55, 0, 0) normal (1, 0, 0) x axis (0, 0, -1)
  circle C1 centre (5, 33) radius 1.7
loft "Loft1" sketch "Case_cut_6_profile_0" + "Case_cut_6_profile_1"
work_plane "WorkPlane3" AlongDistance 23.63
sketch "Case_cut_7_profile_0" plane through (23.63, 0, 0) normal (1, 0, 0) x axis (0, 0, -1)
  circle C1 centre (5, 33) radius 1.7
work_plane "WorkPlane4" AlongDistance 25.03
sketch "Case_cut_7_profile_1" plane through (25.03, 0, 0) normal (1, 0, 0) x axis (0, 0, -1)
  circle C1 centre (5, 33) radius 3.1
loft "Loft2" sketch "Case_cut_7_profile_0" + "Case_cut_7_profile_1"
sketch "Case_cut_8_sketch" plane through (0, 0, 0) normal (1, 0, 0) x axis (0, 0, -1)
  circle C1 centre (5, 58) radius 1.7
extrude "Extrude10" cut sketch "Case_cut_8_sketch" blind 29.18 from offset -4.05
work_plane "WorkPlane5" AlongDistance -3.95
sketch "Case_cut_9_profile_0" plane through (-3.95, 0, 0) normal (1, 0, 0) x axis (0, 0, -1)
  circle C1 centre (5, 58) radius 3.1
work_plane "WorkPlane6" AlongDistance -2.55
sketch "Case_cut_9_profile_1" plane through (-2.55, 0, 0) normal (1, 0, 0) x axis (0, 0, -1)
  circle C1 centre (5, 58) radius 1.7
loft "Loft3" sketch "Case_cut_9_profile_0" + "Case_cut_9_profile_1"
work_plane "WorkPlane7" AlongDistance 23.63
sketch "Case_cut_10_profile_0" plane through (23.63, 0, 0) normal (1, 0, 0) x axis (0, 0, -1)
  circle C1 centre (5, 58) radius 1.7
work_plane "WorkPlane8" AlongDistance 25.03
sketch "Case_cut_10_profile_1" plane through (25.03, 0, 0) normal (1, 0, 0) x axis (0, 0, -1)
  circle C1 centre (5, 58) radius 3.1
loft "Loft4" sketch "Case_cut_10_profile_0" + "Case_cut_10_profile_1"
work_plane "WorkPlane9" AlongDistance 3.3
sketch "Window_reveal_profile_1" plane through (0, 0, 3.3) normal (0, 0, 1) x axis (1, 0, 0)
  line L1 (17.577, 12.405) -> (3.38, 12.405)
  line L2 (18.177, 67.7) -> (18.177, 13.005)
  line L3 (3.38, 68.3) -> (17.577, 68.3)
  line L4 (2.78, 13.005) -> (2.78, 67.7)
  arc A1 centre (17.577, 13.005) radius 0.6 clockwise from (18.177, 13.005) to (17.577, 12.405)
  arc A2 centre (17.577, 67.7) radius 0.6 clockwise from (17.577, 68.3) to (18.177, 67.7)
  arc A3 centre (3.38, 67.7) radius 0.6 clockwise from (2.78, 67.7) to (3.38, 68.3)
  arc A4 centre (3.38, 13.005) radius 0.6 clockwise from (3.38, 12.405) to (2.78, 13.005)
work_plane "WorkPlane10" AlongDistance 5.5
sketch "Window_reveal_profile_2" plane through (0, 0, 5.5) normal (0, 0, 1) x axis (1, 0, 0)
  line L1 (17.577, 10.105) -> (3.38, 10.105)
  line L2 (20.477, 67.7) -> (20.477, 13.005)
  line L3 (3.38, 70.6) -> (17.577, 70.6)
  line L4 (0.48, 13.005) -> (0.48, 67.7)
  arc A1 centre (17.577, 13.005) radius 2.9 clockwise from (20.477, 13.005) to (17.577, 10.105)
  arc A2 centre (17.577, 67.7) radius 2.9 clockwise from (17.577, 70.6) to (20.477, 67.7)
  arc A3 centre (3.38, 67.7) radius 2.9 clockwise from (0.48, 67.7) to (3.38, 70.6)
  arc A4 centre (3.38, 13.005) radius 2.9 clockwise from (3.38, 10.105) to (0.48, 13.005)
loft "Loft5" sketch "Window_reveal_profile_1" + "Window_reveal_profile_2"
fillet "Fillet1" radius 0.35
sketch "Lid_outer_sketch" plane through (0, 0, 0) normal (0, 0, 1) x axis (1, 0, 0)
  line L1 (22.53, -2.7) -> (-1.45, -2.7)
  line L2 (25.03, 73.35) -> (25.03, -0.2)
  line L3 (-1.45, 75.85) -> (22.53, 75.85)
  line L4 (-3.95, -0.2) -> (-3.95, 73.35)
  arc A1 centre (22.53, -0.2) radius 2.5 clockwise from (25.03, -0.2) to (22.53, -2.7)
  arc A2 centre (22.53, 73.35) radius 2.5 clockwise from (22.53, 75.85) to (25.03, 73.35)
  arc A3 centre (-1.45, 73.35) radius 2.5 clockwise from (-3.95, 73.35) to (-1.45, 75.85)
  arc A4 centre (-1.45, -0.2) radius 2.5 clockwise from (-1.45, -2.7) to (-3.95, -0.2)
extrude "Extrude1" new body sketch "Lid_outer_sketch" blind 2 from offset -15.6 bodies "NAP_SAU_LIEN_KHOI"
sketch "Lid_location_lip_sketch" plane through (0, 0, 0) normal (0, 0, 1) x axis (1, 0, 0)
  line L1 (22.23, -0.9) -> (-1.15, -0.9)
  line L2 (22.73, 73.55) -> (22.73, -0.4)
  line L3 (-1.15, 74.05) -> (22.23, 74.05)
  line L4 (-1.65, -0.4) -> (-1.65, 73.55)
  arc A1 centre (22.23, -0.4) radius 0.5 clockwise from (22.73, -0.4) to (22.23, -0.9)
  arc A2 centre (22.23, 73.55) radius 0.5 clockwise from (22.23, 74.05) to (22.73, 73.55)
  arc A3 centre (-1.15, 73.55) radius 0.5 clockwise from (-1.65, 73.55) to (-1.15, 74.05)
  arc A4 centre (-1.15, -0.4) radius 0.5 clockwise from (-1.15, -0.9) to (-1.65, -0.4)
extrude "Extrude2" new body sketch "Lid_location_lip_sketch" blind 0.9 from offset -13.6 bodies "Lid_location_lip"
sketch "Lid_lip_hollow_sketch" plane through (0, 0, 0) normal (0, 0, 1) x axis (1, 0, 0)
  line L1 (21.73, 0) -> (-0.65, 0)
  line L2 (21.83, 73.05) -> (21.83, 0.1)
  line L3 (-0.65, 73.15) -> (21.73, 73.15)
  line L4 (-0.75, 0.1) -> (-0.75, 73.05)
  arc A1 centre (21.73, 0.1) radius 0.1 clockwise from (21.83, 0.1) to (21.73, 0)
  arc A2 centre (21.73, 73.05) radius 0.1 clockwise from (21.73, 73.15) to (21.83, 73.05)
  arc A3 centre (-0.65, 73.05) radius 0.1 clockwise from (-0.75, 73.05) to (-0.65, 73.15)
  arc A4 centre (-0.65, 0.1) radius 0.1 clockwise from (-0.65, 0) to (-0.75, 0.1)
extrude "Extrude3" cut sketch "Lid_lip_hollow_sketch" blind 1.2 from offset -13.7
sketch "Lid_support_1_sketch" plane through (0, 0, 0) normal (0, 0, 1) x axis (1, 0, 0)
  line L1 (15.24, -2.7) -> (5.84, -2.7)
  line L2 (15.24, -1.8) -> (15.24, -2.7)
  line L3 (5.84, -1.8) -> (15.24, -1.8)
  line L4 (5.84, -2.7) -> (5.84, -1.8)
extrude "Extrude4" new body sketch "Lid_support_1_sketch" blind 2.9 from offset -13.6 bodies "Lid_support_1"
sketch "Lid_support_2_sketch" plane through (0, 0, 0) normal (0, 0, 1) x axis (1, 0, 0)
  circle C1 centre (3, 42) radius 4.1
extrude "Extrude5" new body sketch "Lid_support_2_sketch" blind 1.2 from offset -13.6 bodies "Lid_support_2"
sketch "Lid_support_3_sketch" plane through (0, 0, 0) normal (0, 0, 1) x axis (1, 0, 0)
  circle C1 centre (18.08, 42) radius 4.1
extrude "Extrude6" new body sketch "Lid_support_3_sketch" blind 1.2 from offset -13.6 bodies "Lid_support_3"
sketch "Lid_support_4_sketch" plane through (0, 0, 0) normal (0, 0, 1) x axis (1, 0, 0)
  circle C1 centre (3, 66) radius 4.1
extrude "Extrude7" new body sketch "Lid_support_4_sketch" blind 1.2 from offset -13.6 bodies "Lid_support_4"
sketch "Lid_support_5_sketch" plane through (0, 0, 0) normal (0, 0, 1) x axis (1, 0, 0)
  circle C1 centre (18.08, 66) radius 4.1
extrude "Extrude8" new body sketch "Lid_support_5_sketch" blind 1.2 from offset -13.6 bodies "Lid_support_5"
combine "Combine1" bodies "Lid_location_lip", "Lid_support_1", "Lid_support_2", "Lid_support_3", "Lid_support_4", "Lid_support_5"
sketch "Lid_cut_1_sketch" plane through (0, 0, 0) normal (0, 0, 1) x axis (1, 0, 0)
  circle C1 centre (3, 42) radius 1.7
extrude "Extrude9" cut sketch "Lid_cut_1_sketch" blind 3.5 from offset -15.7
sketch "Lid_cut_2_sketch" plane through (0, 0, 0) normal (0, 0, 1) x axis (1, 0, 0)
  circle C1 centre (18.08, 42) radius 1.7
extrude "Extrude10" cut sketch "Lid_cut_2_sketch" blind 3.5 from offset -15.7
sketch "Lid_cut_3_sketch" plane through (0, 0, 0) normal (0, 0, 1) x axis (1, 0, 0)
  circle C1 centre (3, 66) radius 1.7
extrude "Extrude11" cut sketch "Lid_cut_3_sketch" blind 3.5 from offset -15.7
sketch "Lid_cut_4_sketch" plane through (0, 0, 0) normal (0, 0, 1) x axis (1, 0, 0)
  circle C1 centre (18.08, 66) radius 1.7
extrude "Extrude12" cut sketch "Lid_cut_4_sketch" blind 3.5 from offset -15.7
sketch "Lid_cut_5_sketch" plane through (0, 0, 0) normal (0, 0, 1) x axis (1, 0, 0)
  circle C1 centre (3, 42) radius 3.1
extrude "Extrude13" cut sketch "Lid_cut_5_sketch" blind 1.85 from offset -15.7
sketch "Lid_cut_6_sketch" plane through (0, 0, 0) normal (0, 0, 1) x axis (1, 0, 0)
  circle C1 centre (18.08, 42) radius 3.1
extrude "Extrude14" cut sketch "Lid_cut_6_sketch" blind 1.85 from offset -15.7
sketch "Lid_cut_7_sketch" plane through (0, 0, 0) normal (0, 0, 1) x axis (1, 0, 0)
  circle C1 centre (3, 66) radius 3.1
extrude "Extrude15" cut sketch "Lid_cut_7_sketch" blind 1.85 from offset -15.7
sketch "Lid_cut_8_sketch" plane through (0, 0, 0) normal (0, 0, 1) x axis (1, 0, 0)
  circle C1 centre (18.08, 66) radius 3.1
extrude "Extrude16" cut sketch "Lid_cut_8_sketch" blind 1.85 from offset -15.7
sketch "Lid_cut_9_sketch" plane through (0, 0, 0) normal (0, 1, 0) x axis (1, 0, 0)
  line L1 (13.54, 8.8) -> (7.54, 8.8)
  line L2 (15.34, 10.8) -> (15.34, 10.6)
  line L3 (7.54, 12.6) -> (13.54, 12.6)
  line L4 (5.74, 10.6) -> (5.74, 10.8)
  arc A1 centre (13.54, 10.6) radius 1.8 clockwise from (15.34, 10.6) to (13.54, 8.8)
  arc A2 centre (13.54, 10.8) radius 1.8 clockwise from (13.54, 12.6) to (15.34, 10.8)
  arc A3 centre (7.54, 10.8) radius 1.8 clockwise from (5.74, 10.8) to (7.54, 12.6)
  arc A4 centre (7.54, 10.6) radius 1.8 clockwise from (7.54, 8.8) to (5.74, 10.6)
extrude "Extrude17" cut sketch "Lid_cut_9_sketch" blind 4.1 from offset -3.1
base_feature "Base Feature1"
base_feature "Base Feature1" bodies "NEP_left_9.3", "NEP_right_9.3", "NEP_left_20.0", "NEP_right_20.0", "FRAME_left_33", "FRAME_right_33", "FRAME_left_58", "FRAME_right_58"
base_feature "Base Feature1" bodies "NEP_M3x6_left_9.3", "NEP_M3x6_right_9.3", "NEP_M3x6_left_20.0", "NEP_M3x6_right_20.0", "FRAME_DIN7991_M3x8_left_33", "FRAME_DIN7991_M3x8_right_33", "FRAME_DIN7991_M3x8_left_58", "FRAME_DIN7991_M3x8_right_58"
position "Position3"
as_built_joint "As-built1"
sketch "Case_M3_contact_pad_1_sketch" plane through (0, 0, 0) normal (1, 0, 0) x axis (0, 0, -1)
  circle C1 centre (5, 33) radius 3.8
extrude "Extrude11" new body sketch "Case_M3_contact_pad_1_sketch" blind 0.6 from offset -1.95 bodies "Case_M3_contact_pad_1"
sketch "Case_M3_contact_pad_2_sketch" plane through (0, 0, 0) normal (1, 0, 0) x axis (0, 0, -1)
  circle C1 centre (5, 33) radius 3.8
extrude "Extrude12" new body sketch "Case_M3_contact_pad_2_sketch" blind 0.6 from offset 22.43 bodies "Case_M3_contact_pad_2"
sketch "Case_M3_contact_pad_3_sketch" plane through (0, 0, 0) normal (1, 0, 0) x axis (0, 0, -1)
  circle C1 centre (5, 58) radius 3.8
extrude "Extrude13" new body sketch "Case_M3_contact_pad_3_sketch" blind 0.6 from offset -1.95 bodies "Case_M3_contact_pad_3"
sketch "Case_M3_contact_pad_4_sketch" plane through (0, 0, 0) normal (1, 0, 0) x axis (0, 0, -1)
  circle C1 centre (5, 58) radius 3.8
extrude "Extrude14" new body sketch "Case_M3_contact_pad_4_sketch" blind 0.6 from offset 22.43 bodies "Case_M3_contact_pad_4"
combine "Combine2" bodies "Case_M3_contact_pad_1", "Case_M3_contact_pad_2", "Case_M3_contact_pad_3", "Case_M3_contact_pad_4"
sketch "M3_pad_clearance_33_sketch" plane through (0, 0, 0) normal (1, 0, 0) x axis (0, 0, -1)
  circle C1 centre (5, 33) radius 1.7
extrude "Extrude15" cut sketch "M3_pad_clearance_33_sketch" blind 29.18 from offset -4.05
sketch "M3_pad_clearance_58_sketch" plane through (0, 0, 0) normal (1, 0, 0) x axis (0, 0, -1)
  circle C1 centre (5, 58) radius 1.7
extrude "Extrude16" cut sketch "M3_pad_clearance_58_sketch" blind 29.18 from offset -4.05
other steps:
create_component "CreateComponent1"
create_component "CreateComponent2"
create_component "CreateComponent3"
create_component "CreateComponent4"
create_component "CreateComponent5"
create_component "CreateComponent1"
create_component "CreateComponent6"
create_component "CreateComponent7"
create_component "CreateComponent8"
named bodies: "TFT_PCB_proxy_thickness_1p6", "LCD_proxy", "01_KHUNG_HA_ESP", "frame_part_2", "frame_part_3", "frame_part_4", "frame_part_5", "frame_part_6", "frame_part_7", "frame_part_8", "frame_part_9", "frame_part_10", "frame_part_11", "frame_part_12", "frame_part_13", "frame_part_14", "frame_part_15", "frame_part_16", "frame_part_17", "frame_part_18", "frame_part_19", "frame_part_20", "frame_part_21", "frame_part_22", "frame_part_23", "frame_part_24", "frame_part_25", "frame_part_26", "frame_part_27", "frame_part_28", "frame_part_29", "02_NEP_ESP", "keeper_part_2", "keeper_part_3", "keeper_part_4", "keeper_part_5", "keeper_part_6", "keeper_part_7", "keeper_part_8", "keeper_part_9", "keeper_part_10", "keeper_part_11", "keeper_part_12", "keeper_part_13", "keeper_part_14", "keeper_part_15", "keeper_part_16", "keeper_part_17", "keeper_part_18", "keeper_part_19", "keeper_part_20", "keeper_part_21", "keeper_part_22", "keeper_part_23", "keeper_part_24", "keeper_part_25", "keeper_part_26", "keeper_part_27", "keeper_part_28", "keeper_part_29"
